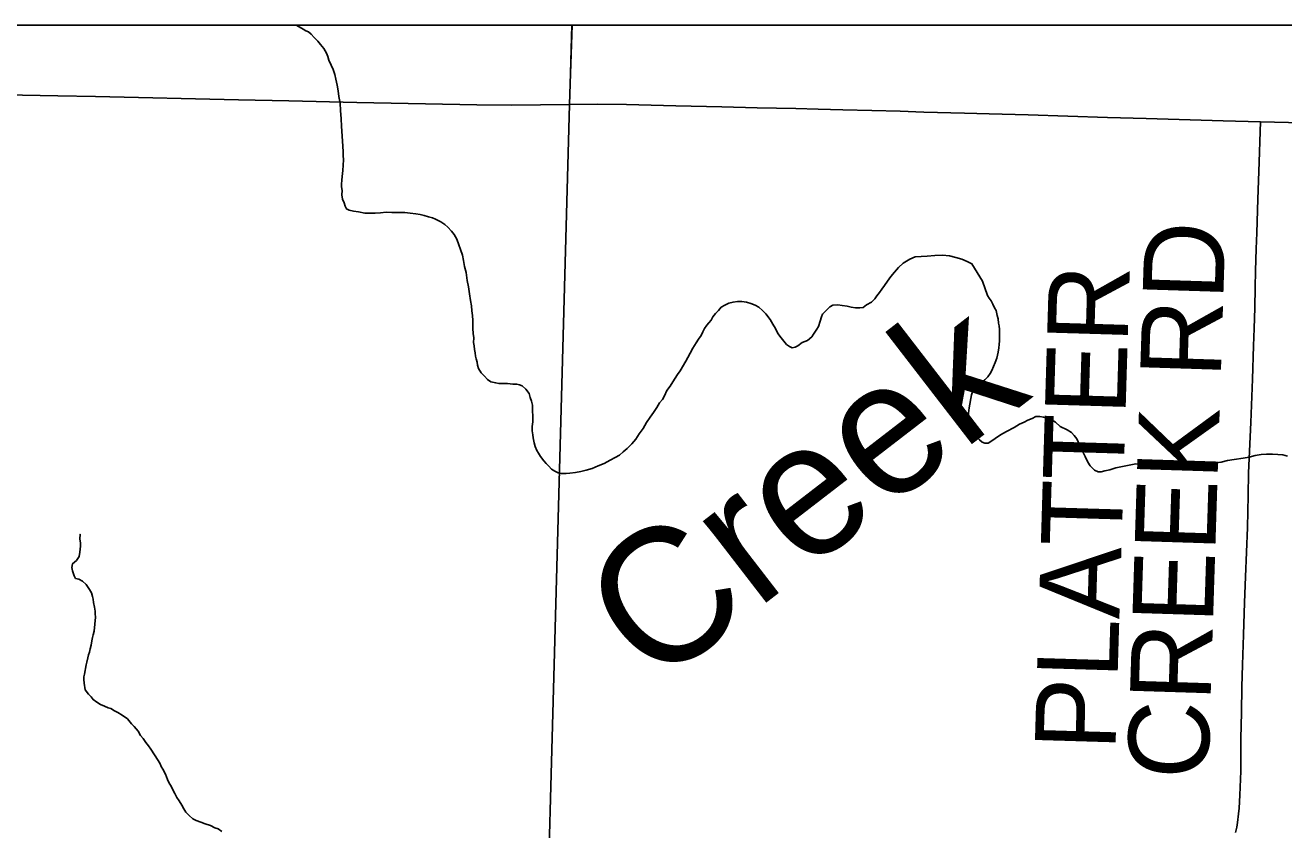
# Model space of a CAD drawing. Extents: x 0 to 64.8, y -5 to 22.
# Drawn here: x 5.41 to 6.296, y 20.333 to 20.9 of the extents above; entities that cross this region are included whole.
import ezdxf

# ---------------------------------------------------------------- set-up
doc = ezdxf.new("R2010")
doc.units = 0
for name, color, linetype in [('GM_X_Adjacent_County', 7, 'Continuous'), ('GM_X_County', 7, 'Continuous'), ('GM_X_County_Road', 7, 'Continuous'), ('GM_X_Minor_River', 7, 'Continuous'), ('GM_X_Minor_River_Text', 7, 'Continuous'), ('GM_X_Township', 7, 'Continuous'), ('GM_X_Township_Road', 7, 'Continuous'), ('GM_X_Township_Road_Text', 7, 'Continuous'), ('SH_Data', 7, 'Continuous')]:
    doc.layers.add(name, color=color, linetype=linetype)

msp = doc.modelspace()

# ---------------------------------------------------------------- linework, layer by layer
at = {"layer": 'GM_X_Adjacent_County'}
msp.add_lwpolyline([(8.9, 19.78096), (8.9, 20.9), (2.1, 20.9), (2.1, 19.91762)], dxfattribs=at)
at = {"layer": 'GM_X_County'}
msp.add_lwpolyline([(8.9, 19.78096), (8.9, 20.9), (2.1, 20.9), (2.1, 19.91762)], dxfattribs=at)
at = {"layer": 'GM_X_County_Road'}
for points in [[(5.7929, 20.84415), (5.79356, 20.86593), (5.79459, 20.9)], [(4.78473, 20.86406), (4.79913, 20.86376), (4.86377, 20.86233), (4.90354, 20.86136), (4.95949, 20.86018), (5.06018, 20.85788), (5.12668, 20.85631), (5.16336, 20.85561), (5.24912, 20.85393), (5.2889, 20.85299), (5.31936, 20.85221), (5.37033, 20.85137), (5.43248, 20.85032), (5.45922, 20.84983), (5.5599, 20.8474), (5.59531, 20.84667), (5.64317, 20.84555), (5.7277, 20.84387), (5.75196, 20.84367), (5.7929, 20.84415)], [(5.7929, 20.84415), (5.81245, 20.84423), (5.83298, 20.84405), (5.86779, 20.84327), (5.90011, 20.84236), (5.92496, 20.84177), (5.9523, 20.8412), (5.96784, 20.84085), (5.98524, 20.84045), (6.00575, 20.8399), (6.02563, 20.83931), (6.0424, 20.83873), (6.07094, 20.8379), (6.08833, 20.83752), (6.11569, 20.83683), (6.17161, 20.83504), (6.19896, 20.83426), (6.25301, 20.83263), (6.27934, 20.83194)], [(6.27934, 20.83194), (6.30895, 20.83117), (6.35805, 20.82985), (6.39161, 20.82885), (6.4295, 20.82749), (6.44503, 20.82699), (6.46677, 20.82623), (6.50589, 20.82495), (6.52639, 20.82427), (6.54876, 20.82363), (6.58357, 20.82265), (6.61709, 20.8214), (6.66022, 20.82017), (6.70221, 20.81872), (6.73391, 20.81781), (6.77306, 20.81634), (6.7807, 20.81605)]]:
    msp.add_lwpolyline(points, dxfattribs=at)
at = {"layer": 'GM_X_Minor_River'}
for points in [[(5.60046, 20.9), (5.60257, 20.89876), (5.60521, 20.89719), (5.60709, 20.89602), (5.60898, 20.89523), (5.61086, 20.89368), (5.6131, 20.89137), (5.61572, 20.88866), (5.61759, 20.88635), (5.61983, 20.88366), (5.62168, 20.88021), (5.62278, 20.87791), (5.6235, 20.87524), (5.62497, 20.87179), (5.62644, 20.86873), (5.62753, 20.86529), (5.62824, 20.86186), (5.62931, 20.85766), (5.63001, 20.85385), (5.63032, 20.84967), (5.63139, 20.84509), (5.63169, 20.83977), (5.63198, 20.83406), (5.63228, 20.82874), (5.6332, 20.81466), (5.63352, 20.81086), (5.63348, 20.8082), (5.63381, 20.80515), (5.63337, 20.80136), (5.63331, 20.79756), (5.63287, 20.79339), (5.63244, 20.79073), (5.6324, 20.78807), (5.63237, 20.78618), (5.63271, 20.78351), (5.63266, 20.78047), (5.633, 20.77742), (5.6341, 20.77475), (5.63482, 20.77245), (5.63593, 20.77054), (5.63782, 20.76975), (5.64085, 20.76894), (5.64427, 20.7685), (5.64882, 20.76767), (5.65262, 20.76761), (5.65604, 20.76755), (5.65985, 20.76787), (5.66366, 20.76819), (5.66784, 20.76813), (5.67279, 20.76804), (5.67697, 20.76798), (5.68077, 20.76754), (5.68457, 20.76709), (5.6876, 20.76667), (5.69063, 20.76586), (5.69366, 20.76505), (5.69631, 20.76425), (5.69858, 20.76345), (5.70235, 20.76149), (5.70499, 20.75955), (5.70724, 20.75761), (5.70986, 20.75491), (5.71172, 20.7526), (5.71357, 20.74915)], [(5.71357, 20.74915), (5.71758, 20.73806), (5.71828, 20.73425), (5.71898, 20.73006), (5.72005, 20.72586), (5.72072, 20.72015), (5.72179, 20.71558), (5.72248, 20.71063), (5.72317, 20.70605), (5.72387, 20.70224), (5.72419, 20.69882), (5.72452, 20.69539), (5.72485, 20.69197), (5.72481, 20.68931), (5.72476, 20.68627), (5.72508, 20.68284), (5.72542, 20.6798), (5.72536, 20.67638), (5.72571, 20.67409), (5.72605, 20.67143), (5.72639, 20.66914), (5.72674, 20.66686), (5.72709, 20.66495), (5.72781, 20.66266), (5.72815, 20.66037), (5.72888, 20.65808), (5.73073, 20.65501), (5.73298, 20.6527), (5.73522, 20.65038), (5.73748, 20.64882), (5.74089, 20.64801), (5.74317, 20.64759), (5.74621, 20.64754), (5.74925, 20.64749), (5.75305, 20.64705), (5.75571, 20.64701), (5.75761, 20.6466), (5.7595, 20.64581), (5.76212, 20.64348), (5.76435, 20.64041), (5.76508, 20.63774), (5.76617, 20.63506), (5.76689, 20.63239), (5.76709, 20.6206), (5.76665, 20.61719), (5.76661, 20.61415), (5.76695, 20.61149), (5.76729, 20.6092), (5.768, 20.60577), (5.76871, 20.6031), (5.76982, 20.60042), (5.77093, 20.5985), (5.77241, 20.5962), (5.77465, 20.59312), (5.77652, 20.59119), (5.77839, 20.58926), (5.78026, 20.58733), (5.78252, 20.58577), (5.78478, 20.5846), (5.78706, 20.58418), (5.79048, 20.58413), (5.79315, 20.58446), (5.79696, 20.58478), (5.80077, 20.58548), (5.80459, 20.58656), (5.80879, 20.58763), (5.81301, 20.58946), (5.81722, 20.5913), (5.82144, 20.59351), (5.82489, 20.59535), (5.82796, 20.5972), (5.83066, 20.59944), (5.83336, 20.60168), (5.83683, 20.60504), (5.83955, 20.60841), (5.84189, 20.61218), (5.84461, 20.61593), (5.84696, 20.62008), (5.84968, 20.62383), (5.85202, 20.62721), (5.85435, 20.6306), (5.85631, 20.63398), (5.85824, 20.63623), (5.8598, 20.63887), (5.86139, 20.64264), (5.86371, 20.64564), (5.86566, 20.64865), (5.86723, 20.65129), (5.86879, 20.65392), (5.87073, 20.65655), (5.87464, 20.66333), (5.87621, 20.66596), (5.87778, 20.66898), (5.87973, 20.67237), (5.88207, 20.67613), (5.88363, 20.67876), (5.88558, 20.68139), (5.88676, 20.68403), (5.88793, 20.68629), (5.88949, 20.68855), (5.89104, 20.69042)], [(5.89104, 20.69042), (5.89259, 20.6923), (5.89377, 20.69456), (5.89571, 20.69681), (5.89764, 20.69906), (5.89958, 20.70131), (5.90227, 20.70278), (5.90495, 20.70426), (5.90801, 20.70497), (5.91106, 20.7053), (5.9141, 20.70525), (5.91751, 20.70481), (5.92054, 20.70401), (5.92357, 20.70282), (5.92621, 20.70126), (5.92883, 20.69893), (5.93108, 20.69662), (5.93406, 20.69277), (5.93591, 20.68932), (5.93776, 20.68625), (5.93961, 20.6828), (5.94184, 20.67972), (5.94371, 20.67741), (5.94557, 20.6751), (5.94783, 20.67354), (5.94972, 20.67275), (5.95163, 20.6731), (5.95355, 20.67421), (5.95663, 20.67644), (5.96045, 20.6779), (5.96354, 20.68051), (5.96471, 20.68239), (5.96704, 20.68577), (5.96821, 20.68766), (5.96941, 20.69143), (5.97022, 20.69446), (5.97101, 20.69635), (5.97604, 20.70159), (5.97834, 20.70269), (5.98177, 20.70302), (5.9848, 20.70259), (5.98822, 20.70215), (5.99125, 20.70134), (5.99429, 20.70091), (5.99733, 20.70086), (5.99962, 20.7012), (6.00193, 20.70307), (6.00538, 20.70491), (6.0077, 20.70716), (6.00925, 20.70941), (6.01119, 20.71166), (6.01275, 20.71391), (6.01469, 20.71654), (6.01664, 20.71955), (6.01898, 20.72293), (6.02168, 20.72593), (6.0244, 20.7293), (6.02787, 20.73229), (6.03248, 20.73525), (6.03631, 20.73671), (6.0405, 20.73702), (6.04469, 20.73733), (6.05002, 20.73763), (6.05535, 20.73792), (6.06028, 20.73746), (6.06483, 20.73625), (6.06899, 20.73504), (6.07277, 20.73346), (6.07617, 20.73188), (6.08359, 20.7196), (6.08723, 20.70966), (6.08834, 20.70774), (6.08983, 20.70582), (6.09094, 20.70352), (6.09204, 20.70084), (6.09315, 20.69893), (6.09386, 20.6955), (6.09458, 20.6932), (6.09492, 20.69016), (6.09527, 20.68825), (6.0956, 20.68559), (6.09556, 20.68255), (6.09551, 20.67989), (6.09548, 20.67761), (6.09544, 20.67495), (6.09502, 20.67267), (6.09459, 20.66964), (6.09377, 20.66548), (6.09258, 20.66245), (6.09139, 20.65943), (6.09021, 20.65679), (6.08903, 20.65453), (6.08747, 20.65228)], [(6.08747, 20.65228), (6.08516, 20.65004), (6.08285, 20.64817), (6.08053, 20.64593), (6.0786, 20.64406), (6.07666, 20.64181), (6.07586, 20.63955), (6.0742, 20.63045), (6.07376, 20.62666), (6.07371, 20.62362), (6.07406, 20.62134), (6.07441, 20.61943), (6.07476, 20.61752), (6.07549, 20.61561), (6.07733, 20.61178), (6.07921, 20.61023), (6.08145, 20.60791), (6.08333, 20.60636), (6.08522, 20.60557), (6.0875, 20.60554), (6.08942, 20.60665), (6.0925, 20.60888), (6.09634, 20.61147), (6.10056, 20.61368), (6.10593, 20.61664), (6.10977, 20.61885), (6.11284, 20.62033), (6.11552, 20.6218), (6.11858, 20.62289), (6.12127, 20.62437), (6.12393, 20.62433), (6.12659, 20.6239), (6.12924, 20.6231), (6.13226, 20.62191), (6.1349, 20.62034), (6.13827, 20.61725), (6.14318, 20.61489), (6.14619, 20.61294), (6.14807, 20.61101), (6.14993, 20.6087), (6.15103, 20.6064), (6.1525, 20.60296), (6.15398, 20.5999), (6.15582, 20.59607), (6.15766, 20.59223), (6.15952, 20.58954), (6.16252, 20.58646), (6.16516, 20.58527), (6.16706, 20.58524), (6.16973, 20.58596), (6.17317, 20.58666), (6.17738, 20.58812), (6.19149, 20.59092), (6.19644, 20.59084), (6.20099, 20.59039), (6.20669, 20.58992), (6.21163, 20.58946), (6.21733, 20.58898), (6.22303, 20.58889), (6.22913, 20.58955), (6.23522, 20.59021), (6.24094, 20.59088), (6.24628, 20.59155), (6.25161, 20.59223), (6.25619, 20.59329), (6.26077, 20.59398), (6.26725, 20.59501), (6.27145, 20.5957), (6.27564, 20.59678), (6.27984, 20.59747), (6.28365, 20.59778), (6.28783, 20.59772), (6.29164, 20.59766), (6.29505, 20.59722), (6.29846, 20.59641)], [(5.44824, 20.54136), (5.44822, 20.54023), (5.44824, 20.54136), (5.44819, 20.53795), (5.44852, 20.53528), (5.44849, 20.533), (5.44804, 20.52883), (5.44761, 20.5258), (5.44567, 20.52279), (5.44297, 20.52055), (5.44255, 20.5179), (5.44289, 20.51561), (5.44398, 20.51217), (5.44509, 20.51025), (5.44736, 20.50984), (5.45, 20.50828), (5.45263, 20.50595), (5.45486, 20.5025), (5.45634, 20.5002), (5.45706, 20.49752), (5.45741, 20.49562), (5.45776, 20.49333), (5.45846, 20.4899), (5.4588, 20.48723), (5.45877, 20.48534), (5.45912, 20.48305), (5.45866, 20.47812), (5.4582, 20.47318), (5.4574, 20.47054), (5.45699, 20.46864), (5.45657, 20.46637), (5.45614, 20.46334), (5.45534, 20.46069), (5.45493, 20.45842), (5.45414, 20.45653), (5.45372, 20.45426), (5.45291, 20.45123), (5.4525, 20.44934), (5.45126, 20.4429), (5.45085, 20.441), (5.45082, 20.4391), (5.45116, 20.43644), (5.45185, 20.43187), (5.45408, 20.42879), (5.45595, 20.42686), (5.45745, 20.42494), (5.46008, 20.42299), (5.46271, 20.42143), (5.46536, 20.42025), (5.468, 20.41907), (5.4699, 20.41866), (5.47253, 20.41709), (5.4748, 20.41592), (5.47781, 20.41397), (5.48157, 20.41125), (5.48456, 20.40778), (5.48643, 20.40585), (5.48905, 20.40277), (5.4909, 20.3997), (5.49277, 20.39739), (5.49463, 20.3947), (5.49649, 20.39239), (5.49798, 20.39009), (5.50318, 20.38202), (5.50466, 20.37972), (5.50539, 20.37781), (5.5065, 20.37589), (5.50835, 20.37244), (5.50908, 20.37053), (5.50981, 20.36862), (5.51091, 20.36594), (5.5124, 20.36401), (5.5135, 20.36134), (5.51498, 20.35865), (5.51646, 20.35597), (5.51795, 20.35366), (5.5198, 20.3506), (5.52128, 20.34791), (5.52277, 20.34561), (5.52501, 20.34329), (5.52764, 20.34097), (5.5299, 20.33979), (5.53331, 20.3386), (5.53633, 20.33741), (5.54011, 20.33621), (5.54313, 20.33464), (5.5454, 20.33384), (5.54803, 20.3319)]]:
    msp.add_lwpolyline(points, dxfattribs=at)
at = {"layer": 'GM_X_Township'}
for points in [[(5.7946, 20.9), (2.1, 20.9), (2.1, 19.91762)], [(5.389, 19.84945), (5.43252, 19.84875), (5.46984, 19.84785), (5.65344, 19.8431), (5.76533, 19.84042), (5.7929, 20.84415), (5.79356, 20.86592), (5.7946, 20.9)], [(5.7946, 20.9), (5.79356, 20.86592), (5.7929, 20.84415), (5.76533, 19.84042), (5.77168, 19.84027), (5.78773, 19.84007), (5.80115, 19.83966), (5.81576, 19.8392), (6.48839, 19.82233), (6.75027, 19.81474), (6.76179, 19.81479), (6.79501, 19.81422), (6.90684, 19.8113), (6.9845, 19.80949)], [(8.9, 19.78096), (8.9, 20.9), (5.7946, 20.9)]]:
    msp.add_lwpolyline(points, dxfattribs=at)
at = {"layer": 'GM_X_Township_Road'}
for points in [[(6.26396, 20.34438), (6.26435, 20.34845), (6.26482, 20.35768), (6.26542, 20.37445), (6.2656, 20.39759), (6.26594, 20.41588), (6.26625, 20.4338), (6.2667, 20.44932), (6.26739, 20.47042), (6.26816, 20.4934), (6.26877, 20.51141), (6.27008, 20.54619), (6.27063, 20.56856), (6.27084, 20.58471), (6.27251, 20.62007), (6.27369, 20.65052), (6.27434, 20.67407), (6.27478, 20.6862), (6.27527, 20.70095), (6.27566, 20.7152), (6.27593, 20.727), (6.27634, 20.74253), (6.27666, 20.75372), (6.27738, 20.77732), (6.27845, 20.8034), (6.27913, 20.82515), (6.27934, 20.83194)], [(6.26174, 20.33134), (6.26272, 20.33512), (6.26321, 20.33841), (6.26396, 20.34438)]]:
    msp.add_lwpolyline(points, dxfattribs=at)
at = {"layer": 'SH_Data'}
msp.add_line((2.1, 20.9), (8.9, 20.9), dxfattribs=at)

# ---------------------------------------------------------------- texts
at = {"layer": 'GM_X_Minor_River_Text'}
msp.add_text('Creek', height=0.094733, rotation=37.64326, dxfattribs=at).set_placement((5.85198, 20.43195))
at = {"layer": 'GM_X_Township_Road_Text'}
for s, rotation, p in [('CREEK RD', 88.18504, (6.24237, 20.36827)), ('PLATTER', 88.27866, (6.17715, 20.38854))]:
    msp.add_text(s, height=0.056818, rotation=rotation, dxfattribs=at).set_placement(p)

doc.saveas('drawing.dxf')
